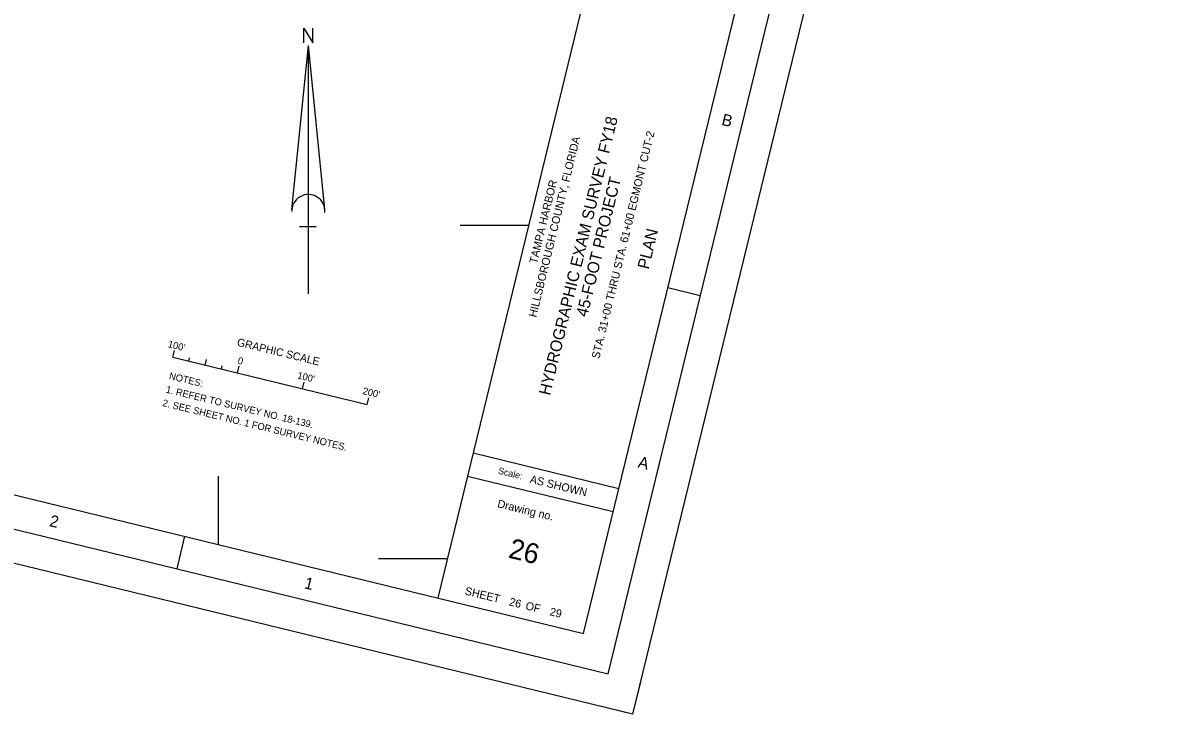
# Model space of a CAD drawing. Extents: x 406346 to 411426, y 1189267 to 1193612.
# Drawn here: x 409707 to 411426, y 1189267 to 1190303 of the extents above; entities that cross this region are included whole.
import ezdxf

# ---------------------------------------------------------------- set-up
doc = ezdxf.new("R2010")
doc.units = 0
for name, color, linetype in [('G-ANNO-NPLT', 7, 'Continuous'), ('G-ANNO-TEXT-DRWG', 7, 'Continuous'), ('G-ANNO-TEXT-PROJ', 7, 'Continuous'), ('G-ANNO-TEXT-TTLB', 7, 'Continuous'), ('G-ANNO-TTLB', 7, 'Continuous'), ('V-ANNO-NOTE', 7, 'Continuous'), ('V-ANNO-SYMB', 7, 'Continuous'), ('V-TOPO-COOR-STAT', 7, 'Continuous')]:
    doc.layers.add(name, color=color, linetype=linetype)

msp = doc.modelspace()

# ---------------------------------------------------------------- linework, layer by layer
at = {"layer": 'G-ANNO-NPLT'}
msp.add_lwpolyline([(407151.7, 1193612.5), (411426.4, 1192570), (410620.9, 1189266.8), (406346.2, 1190309.3)], close=True, dxfattribs=at)
msp.add_lwpolyline([(410632.7, 1189315.4), (410620.9, 1189266.8), (410572.3, 1189278.7)], dxfattribs=at)
at = {"layer": 'G-ANNO-TTLB'}
for p, q in [((411086.9, 1192549.9), (410328.8, 1189441)), ((410722.3, 1189893.9), (410673.7, 1189905.8)), ((410381.8, 1189658.4), (410600.4, 1189605.1)), ((410373.3, 1189623.7), (410592, 1189570.4)), ((409938.1, 1189484.8), (409949.9, 1189533.4))]:
    msp.add_line(p, q, dxfattribs=at)
for points in [[(406406.6, 1190346), (410584.1, 1189327.2), (411366, 1192533.3), (407188.5, 1193552.1)], [(411305.6, 1192496.5), (407298, 1193473.9), (406539.9, 1190365), (410547.4, 1189387.7)]]:
    msp.add_lwpolyline(points, close=True, dxfattribs=at)
at = {"layer": 'V-ANNO-NOTE'}
for p, q in [((409931.6, 1189802.1), (409934.1, 1189812.2)), ((409931.6, 1189802.1), (410223, 1189731)), ((409955.9, 1189796.1), (409957, 1189800.8)), ((409980.2, 1189790.2), (409982.2, 1189798.5)), ((410004.5, 1189784.3), (410005.6, 1189788.9)), ((410028.7, 1189778.4), (410031.2, 1189788.5)), ((410028.7, 1189778.4), (410031.2, 1189788.5)), ((410028.7, 1189778.4), (410029.9, 1189783.2)), ((410125.9, 1189754.7), (410128.4, 1189764.8)), ((410223, 1189731), (410225.5, 1189741.1))]:
    msp.add_line(p, q, dxfattribs=at)
at = {"layer": 'V-ANNO-SYMB'}
for p, q in [((410110.2, 1190023.7), (410134.9, 1190269.5)), ((410134.9, 1189897.1), (410134.9, 1190269.5)), ((410159.6, 1190023.7), (410134.9, 1190269.5)), ((410146.6, 1189997.7), (410121.8, 1189997.7))]:
    msp.add_line(p, q, dxfattribs=at)
msp.add_lwpolyline([(410128, 1190273.5), (410128, 1190295.2), (410141.5, 1190273.5), (410141.5, 1190295.2)], dxfattribs=at)
msp.add_arc((410134.9, 1190021.2), 24.8, 355.2984, 182.0673, dxfattribs=at)
at = {"layer": 'V-TOPO-COOR-STAT'}
for p, q in [((410362.2, 1190000), (410465.1, 1190000)), ((410000, 1189520.9), (410000, 1189623.8)), ((410240.2, 1189500), (410343.2, 1189500))]:
    msp.add_line(p, q, dxfattribs=at)

# ---------------------------------------------------------------- texts
at = {"layer": 'G-ANNO-TEXT-DRWG'}
for s, height, rotation, p in [('STA. 31+00 THRU STA. 61+00 EGMONT CUT-2', 12, 76.2946, (410570.9, 1189798.9)), ('PLAN', 17.5, 76.2946, (410644.9, 1189932.9)), ('26', 30, 346.2946, (410433.4, 1189501.7)), (' 26          29', 12, 346.2946, (410430.8, 1189431))]:
    msp.add_text(s, height=height, rotation=rotation, dxfattribs=at).set_placement(p)
at = {"layer": 'G-ANNO-TEXT-PROJ'}
for s, height, p in [('HYDROGRAPHIC EXAM SURVEY FY18', 17.5, (410497.1, 1189743.7)), ('HILLSBOROUGH COUNTY, FLORIDA', 12, (410476.5, 1189861)), ('TAMPA HARBOR', 12, (410477.6, 1189941.4)), ('45-FOOT PROJECT', 17.5, (410552.8, 1189861.4))]:
    msp.add_text(s, height=height, rotation=76.2946, dxfattribs=at).set_placement(p)
at = {"layer": 'G-ANNO-TEXT-TTLB'}
for s, height, p in [('Scale:', 10, (410418.6, 1189627.4)), ('AS SHOWN', 12, (410466.1, 1189613.8)), ('Drawing no.', 12, (410417.4, 1189577.2)), ('SHEET         OF', 12, (410368.6, 1189446.2))]:
    msp.add_text(s, height=height, rotation=346.2946, dxfattribs=at).set_placement(p)
at = {"layer": 'G-ANNO-TTLB'}
for s, p in [('B', (410753.1, 1190150.6)), ('A', (410627.8, 1189636.9)), ('2', (409745.7, 1189548.9)), ('1', (410127.7, 1189455.7))]:
    msp.add_text(s, height=17.5, rotation=346.2946, dxfattribs=at).set_placement(p)
at = {"layer": 'V-ANNO-NOTE'}
for s, height, p in [("100'", 10.42, (409923.6, 1189817.1)), ('GRAPHIC SCALE', 11.666, (410027.2, 1189819.4)), ('0', 10.4, (410028.3, 1189792.3)), ('NOTES:', 10.42, (409925.4, 1189769.4)), ("100'", 10.42, (410117.7, 1189770.2)), ('1. REFER TO SURVEY NO. 18-139.', 10.416, (409920.5, 1189749.1)), ("200'", 10.42, (410215.5, 1189746.9)), ('2. SEE SHEET NO. 1 FOR SURVEY NOTES.', 10.416, (409915.5, 1189728.9))]:
    msp.add_text(s, height=height, rotation=346.2946, dxfattribs=at).set_placement(p)

doc.saveas('drawing.dxf')
